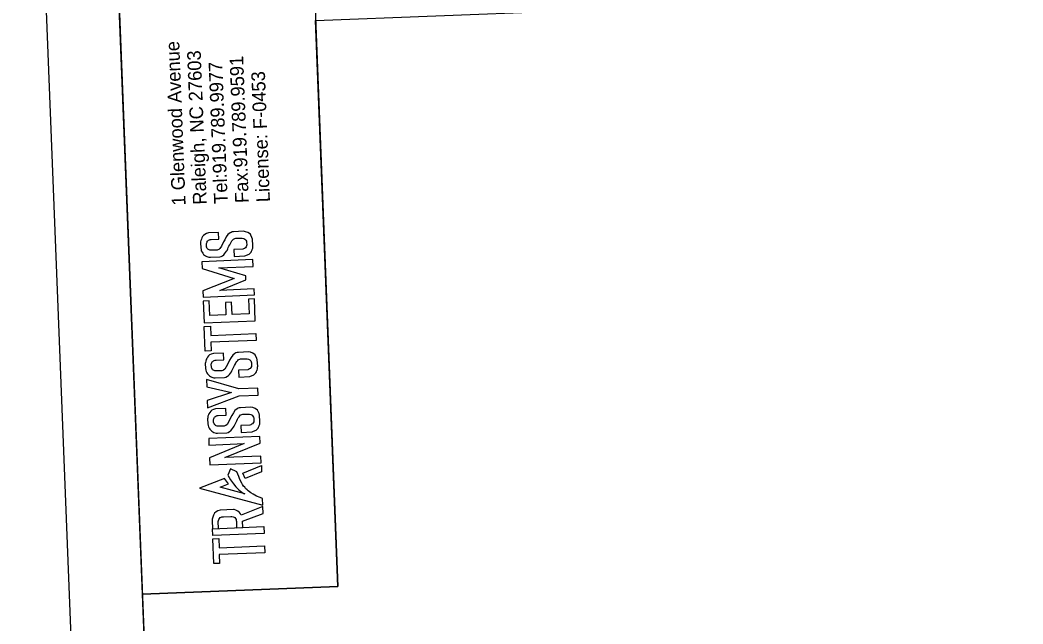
# Model space of a CAD drawing. Extents: x 1627905 to 1629071, y 761064 to 763101.
# Drawn here: x 1627905.2 to 1628247.2, y 762441.1 to 762646.9 of the extents above; entities that cross this region are included whole.
import ezdxf

# ---------------------------------------------------------------- set-up
doc = ezdxf.new("R2010")
doc.units = 0
for name, color, linetype in [('Old_Level_2', 7, 'Continuous'), ('Old_Level_58', 7, 'Continuous'), ('Sheet Clip Boundary CELL', 7, 'Continuous'), ('Sheet Plan And Profile CELL', 7, 'Continuous'), ('Sheet Plot Border Outside CELL', 7, 'Continuous')]:
    doc.layers.add(name, color=color, linetype=linetype)

msp = doc.modelspace()

# ---------------------------------------------------------------- linework, layer by layer
at = {"layer": 'Old_Level_2'}
for points in [[(1627973.01, 762572.22), (1627972.91, 762574.53), (1627969.44, 762574.39), (1627968.74, 762574.17), (1627968.17, 762573.87), (1627967.79, 762573.55), (1627967.45, 762573.17), (1627967.18, 762572.72), (1627967.03, 762572.29), (1627967.03, 762572.29), (1627966.85, 762571.82), (1627966.75, 762571.33), (1627966.68, 762571.01), (1627966.79, 762569.26), (1627966.9, 762568.74), (1627967, 762568.28), (1627967.25, 762567.83), (1627967.48, 762567.44), (1627967.78, 762567.05), (1627968.11, 762566.76), (1627968.48, 762566.53), (1627968.88, 762566.35), (1627969.59, 762566.12), (1627970.11, 762566.09), (1627973.27, 762566.22), (1627973.74, 762566.35), (1627974.23, 762566.6), (1627974.63, 762566.9), (1627974.92, 762567.21), (1627975.25, 762567.68), (1627975.58, 762568.14), (1627975.79, 762568.44), (1627976, 762568.93), (1627976.2, 762569.42), (1627976.44, 762569.82), (1627976.71, 762570.27), (1627976.96, 762570.81), (1627977.16, 762571.25), (1627977.46, 762571.69), (1627977.74, 762572.01), (1627977.97, 762572.27), (1627978.44, 762572.45), (1627978.73, 762572.55), (1627980.97, 762572.6), (1627981.46, 762572.46), (1627981.89, 762572.23), (1627982.19, 762571.92), (1627982.37, 762571.57), (1627982.45, 762571.23), (1627982.51, 762570.27), (1627982.44, 762569.95), (1627982.26, 762569.61), (1627982.07, 762569.27), (1627981.75, 762569.12), (1627981.42, 762568.96), (1627981.15, 762568.84), (1627978.05, 762568.68), (1627978.17, 762566.35), (1627981.87, 762566.53), (1627982.15, 762566.66), (1627983, 762566.97), (1627983.28, 762567.15), (1627983.59, 762567.42), (1627983.95, 762567.81), (1627984.13, 762568.13), (1627984.3, 762568.57), (1627984.36, 762568.73), (1627984.52, 762569.17), (1627984.55, 762569.7), (1627984.58, 762570.1), (1627984.44, 762572.23), (1627984.27, 762572.82), (1627983.87, 762573.63), (1627983.73, 762573.91), (1627982.92, 762574.5), (1627982.12, 762574.8), (1627981.4, 762574.93), (1627977.98, 762574.74), (1627977.51, 762574.71), (1627977.14, 762574.57), (1627976.8, 762574.36), (1627976.06, 762573.79), (1627975.53, 762573.06), (1627974.99, 762572.07), (1627974.58, 762571.3), (1627973.87, 762569.81), (1627973.34, 762569.04), (1627972.93, 762568.69), (1627972.65, 762568.6), (1627972.37, 762568.51), (1627969.93, 762568.46), (1627969.68, 762568.58), (1627969.42, 762568.69), (1627969.26, 762568.86), (1627969.05, 762569.09), (1627968.93, 762569.34), (1627968.82, 762569.6), (1627968.84, 762569.74), (1627968.77, 762569.76), (1627968.74, 762570.72), (1627968.84, 762571), (1627968.94, 762571.28), (1627969.04, 762571.56), (1627969.23, 762571.7), (1627969.5, 762571.89), (1627969.77, 762572), (1627970.04, 762572.1), (1627970.35, 762572.1)], [(1627978.23, 762558.89), (1627967.47, 762554.65), (1627967.66, 762552.45), (1627985.1, 762553.22), (1627985.01, 762555.33), (1627973.34, 762554.81), (1627982.19, 762558.43), (1627982.17, 762559.78), (1627972.93, 762562.48), (1627984.64, 762562.99), (1627984.54, 762565.27), (1627967.14, 762564.52), (1627967.24, 762562.22)], [(1627967.68, 762551.1), (1627967.98, 762543.72), (1627985.39, 762544.42), (1627985.09, 762551.88), (1627983.12, 762551.8), (1627983.32, 762546.76), (1627977.48, 762546.53), (1627977.31, 762550.74), (1627975.24, 762550.66), (1627975.41, 762546.41), (1627969.92, 762546.19), (1627969.72, 762551.19)], [(1627968.36, 762534.04), (1627968.02, 762542.5), (1627970.09, 762542.58), (1627970.21, 762539.47), (1627985.62, 762540.09), (1627985.72, 762537.75), (1627970.21, 762537.12), (1627970.33, 762534.15)], [(1627974.67, 762531.13), (1627974.57, 762533.43), (1627971.1, 762533.29), (1627970.4, 762533.07), (1627969.82, 762532.77), (1627969.45, 762532.45), (1627969.11, 762532.07), (1627968.84, 762531.62), (1627968.69, 762531.19), (1627968.69, 762531.19), (1627968.51, 762530.72), (1627968.41, 762530.23), (1627968.34, 762529.91), (1627968.45, 762528.16), (1627968.56, 762527.64), (1627968.66, 762527.19), (1627968.91, 762526.73), (1627969.14, 762526.34), (1627969.44, 762525.96), (1627969.76, 762525.66), (1627970.14, 762525.43), (1627970.54, 762525.25), (1627971.25, 762525.02), (1627971.77, 762524.99), (1627974.93, 762525.12), (1627975.4, 762525.25), (1627975.89, 762525.5), (1627976.29, 762525.81), (1627976.58, 762526.11), (1627976.91, 762526.58), (1627977.24, 762527.05), (1627977.45, 762527.34), (1627977.66, 762527.83), (1627977.86, 762528.32), (1627978.1, 762528.72), (1627978.37, 762529.17), (1627978.62, 762529.71), (1627978.82, 762530.15), (1627979.12, 762530.59), (1627979.4, 762530.92), (1627979.63, 762531.18), (1627980.1, 762531.35), (1627980.39, 762531.45), (1627982.63, 762531.51), (1627983.12, 762531.36), (1627983.55, 762531.14), (1627983.85, 762530.82), (1627984.03, 762530.47), (1627984.11, 762530.13), (1627984.17, 762529.17), (1627984.09, 762528.85), (1627983.91, 762528.51), (1627983.73, 762528.17), (1627983.4, 762528.02), (1627983.08, 762527.86), (1627982.81, 762527.74), (1627979.7, 762527.58), (1627979.82, 762525.25), (1627983.53, 762525.44), (1627983.81, 762525.56), (1627984.66, 762525.87), (1627984.94, 762526.06), (1627985.25, 762526.32), (1627985.61, 762526.72), (1627985.79, 762527.03), (1627985.96, 762527.47), (1627986.02, 762527.63), (1627986.18, 762528.07), (1627986.21, 762528.6), (1627986.24, 762529), (1627986.1, 762531.13), (1627985.93, 762531.72), (1627985.53, 762532.53), (1627985.39, 762532.81), (1627984.58, 762533.4), (1627983.78, 762533.7), (1627983.06, 762533.83), (1627979.64, 762533.64), (1627979.17, 762533.61), (1627978.8, 762533.47), (1627978.45, 762533.26), (1627977.72, 762532.69), (1627977.19, 762531.96), (1627976.65, 762530.97), (1627976.23, 762530.21), (1627975.53, 762528.71), (1627974.99, 762527.94), (1627974.59, 762527.59), (1627974.31, 762527.5), (1627974.02, 762527.42), (1627971.59, 762527.37), (1627971.33, 762527.48), (1627971.07, 762527.59), (1627970.92, 762527.77), (1627970.71, 762527.99), (1627970.59, 762528.24), (1627970.48, 762528.5), (1627970.5, 762528.65), (1627970.42, 762528.66), (1627970.4, 762529.62), (1627970.5, 762529.9), (1627970.6, 762530.18), (1627970.7, 762530.46), (1627970.89, 762530.6), (1627971.16, 762530.79), (1627971.43, 762530.9), (1627971.7, 762531), (1627972.01, 762531)], [(1627969.04, 762517.29), (1627969.15, 762514.76), (1627979.88, 762518.8), (1627986.41, 762519.09), (1627986.31, 762521.48), (1627979.82, 762521.19), (1627968.72, 762524.41), (1627968.89, 762521.92), (1627977.32, 762519.95)], [(1627975.43, 762512.27), (1627975.34, 762514.58), (1627971.86, 762514.44), (1627971.16, 762514.21), (1627970.59, 762513.91), (1627970.21, 762513.6), (1627969.87, 762513.21), (1627969.6, 762512.76), (1627969.45, 762512.33), (1627969.45, 762512.33), (1627969.27, 762511.87), (1627969.17, 762511.38), (1627969.1, 762511.05), (1627969.21, 762509.31), (1627969.32, 762508.78), (1627969.42, 762508.33), (1627969.67, 762507.88), (1627969.9, 762507.48), (1627970.2, 762507.1), (1627970.53, 762506.8), (1627970.9, 762506.57), (1627971.3, 762506.39), (1627972.01, 762506.17), (1627972.53, 762506.14), (1627975.69, 762506.26), (1627976.16, 762506.4), (1627976.65, 762506.65), (1627977.05, 762506.95), (1627977.34, 762507.26), (1627977.67, 762507.72), (1627978, 762508.19), (1627978.21, 762508.48), (1627978.42, 762508.97), (1627978.62, 762509.46), (1627978.86, 762509.86), (1627979.13, 762510.32), (1627979.38, 762510.85), (1627979.58, 762511.3), (1627979.88, 762511.74), (1627980.16, 762512.06), (1627980.39, 762512.32), (1627980.86, 762512.49), (1627981.16, 762512.6), (1627983.39, 762512.65), (1627983.88, 762512.51), (1627984.31, 762512.28), (1627984.61, 762511.96), (1627984.79, 762511.61), (1627984.87, 762511.28), (1627984.93, 762510.32), (1627984.86, 762509.99), (1627984.68, 762509.65), (1627984.5, 762509.32), (1627984.17, 762509.16), (1627983.84, 762509.01), (1627983.57, 762508.88), (1627980.47, 762508.73), (1627980.59, 762506.39), (1627984.29, 762506.58), (1627984.57, 762506.71), (1627985.42, 762507.01), (1627985.7, 762507.2), (1627986.01, 762507.46), (1627986.37, 762507.86), (1627986.55, 762508.17), (1627986.72, 762508.61), (1627986.78, 762508.77), (1627986.94, 762509.21), (1627986.97, 762509.75), (1627987, 762510.14), (1627986.86, 762512.28), (1627986.69, 762512.87), (1627986.29, 762513.68), (1627986.15, 762513.95), (1627985.34, 762514.54), (1627984.54, 762514.84), (1627983.82, 762514.97), (1627980.4, 762514.78), (1627979.93, 762514.76), (1627979.56, 762514.61), (1627979.22, 762514.41), (1627978.48, 762513.84), (1627977.95, 762513.11), (1627977.41, 762512.11), (1627977, 762511.35), (1627976.29, 762509.86), (1627975.76, 762509.08), (1627975.35, 762508.74), (1627975.07, 762508.65), (1627974.79, 762508.56), (1627972.35, 762508.51), (1627972.1, 762508.62), (1627971.84, 762508.74), (1627971.68, 762508.91), (1627971.47, 762509.13), (1627971.35, 762509.39), (1627971.24, 762509.64), (1627971.26, 762509.79), (1627971.19, 762509.8), (1627971.16, 762510.76), (1627971.26, 762511.04), (1627971.36, 762511.32), (1627971.46, 762511.6), (1627971.65, 762511.74), (1627971.92, 762511.94), (1627972.19, 762512.04), (1627972.46, 762512.14), (1627972.77, 762512.15)], [(1627969.92, 762495.34), (1627987.37, 762496.04), (1627987.28, 762498.28), (1627975, 762497.78), (1627987.12, 762502.72), (1627987.01, 762504.96), (1627969.52, 762504.25), (1627969.61, 762502.08), (1627981.58, 762502.56), (1627969.82, 762497.7)], [(1627966.41, 762487.43), (1627987.99, 762481.61), (1627987.9, 762483.83), (1627987.04, 762484.14), (1627985.86, 762484.66), (1627985.22, 762484.95), (1627984.67, 762485.3), (1627983.89, 762485.8), (1627983.41, 762486.11), (1627983, 762486.47), (1627982.59, 762486.84), (1627982.08, 762487.3), (1627981.79, 762487.7), (1627981.44, 762488.1), (1627981.1, 762488.65), (1627980.8, 762489.13), (1627980.18, 762490.32), (1627979.74, 762491.3), (1627979.11, 762492.92), (1627976.93, 762493.97), (1627976.06, 762491.76), (1627977, 762490.17), (1627977.97, 762488.83), (1627978.8, 762487.88), (1627979.25, 762487.37), (1627979.83, 762486.86), (1627980.42, 762486.35), (1627980.86, 762485.97), (1627981.52, 762485.61), (1627981.89, 762485.42), (1627973.42, 762487.72), (1627976.27, 762488.83), (1627974.93, 762490.67)], [(1627982, 762490.66), (1627981.16, 762492.54), (1627987.51, 762495.06), (1627987.51, 762492.96)], [(1627972.9, 762473.65), (1627972.8, 762476.03), (1627972.84, 762476.34), (1627972.99, 762476.74), (1627973.19, 762477.08), (1627973.46, 762477.32), (1627973.78, 762477.49), (1627974.03, 762477.62), (1627974.61, 762477.64), (1627977.1, 762477.75), (1627977.43, 762477.7), (1627977.88, 762477.64), (1627978.18, 762477.52), (1627978.44, 762477.33), (1627978.67, 762477.07), (1627978.84, 762476.65), (1627978.89, 762476.32), (1627978.95, 762476), (1627979.04, 762473.9), (1627981.15, 762473.99), (1627981.05, 762476.09), (1627988.11, 762478.74), (1627987.99, 762481.16), (1627980.57, 762478.21), (1627980.42, 762478.59), (1627979.99, 762479.11), (1627979.44, 762479.57), (1627978.8, 762479.9), (1627978.16, 762480.08), (1627977.97, 762480.06), (1627973.41, 762479.92), (1627972.67, 762479.69), (1627972.01, 762479.3), (1627971.55, 762478.87), (1627971.1, 762478.16), (1627970.91, 762477.47), (1627970.71, 762476.79), (1627970.72, 762476.38), (1627970.81, 762473.56)], [(1627970.91, 762471.25), (1627970.81, 762473.56), (1627988.36, 762474.27), (1627988.46, 762471.96)], [(1627971.28, 762461.64), (1627970.94, 762470.1), (1627973.01, 762470.18), (1627973.14, 762467.07), (1627988.55, 762467.69), (1627988.64, 762465.35), (1627973.13, 762464.72), (1627973.25, 762461.75)]]:
    msp.add_lwpolyline(points, close=True, dxfattribs=at)
at = {"layer": 'Old_Level_58'}
msp.add_lwpolyline([(1627946.91, 762451.28), (1627939.02, 762651.17), (1628005.66, 762653.8), (1628013.55, 762453.91)], close=True, dxfattribs=at)
at = {"layer": 'Sheet Clip Boundary CELL'}
msp.add_lwpolyline([(1628129.05, 762651.6), (1628122.74, 762811.67), (1628982.18, 762845.56), (1629039.43, 761393.61), (1627990.25, 761352.23), (1627946.91, 762451.28), (1628013.55, 762453.91), (1628005.94, 762646.74)], close=True, dxfattribs=at)
at = {"layer": 'Sheet Plan And Profile CELL'}
msp.add_lwpolyline([(1627931.14, 762851.07), (1627990.25, 761352.23), (1629039.43, 761393.61), (1628980.33, 762892.44)], close=True, dxfattribs=at)
at = {"layer": 'Sheet Plot Border Outside CELL'}
msp.add_lwpolyline([(1629071.31, 761219.73), (1629004.32, 762918.41), (1627905.18, 762875.06), (1627972.16, 761176.38)], close=True, dxfattribs=at)

# ---------------------------------------------------------------- texts
at = {"layer": 'Old_Level_2'}
for s, p in [('1 Glenwood Avenue', (1627961.66, 762583.81)), ('Raleigh, NC 27603', (1627968.85, 762584.1)), ('Fax:919.789.9591', (1627983.23, 762584.66)), ('Tel:919.789.9977 ', (1627976.04, 762584.38)), ('License: F-0453', (1627990.42, 762584.95))]:
    msp.add_text(s, height=4.6576, rotation=92.2582, dxfattribs=at).set_placement(p)

doc.saveas('drawing.dxf')
